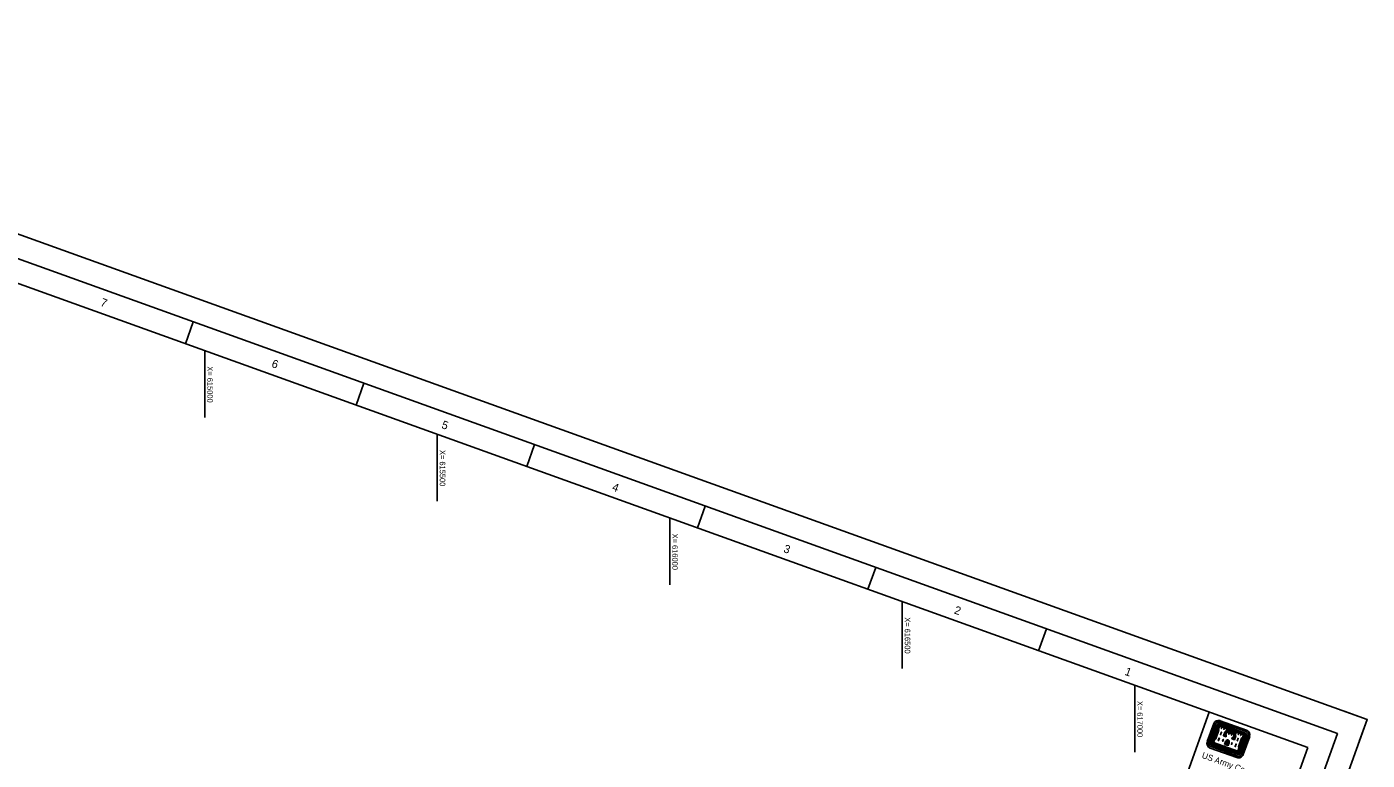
# Model space of a CAD drawing. Extents: x 612209 to 617500, y 780934 to 785622.
# Drawn here: x 614617 to 617500, y 784046 to 785622 of the extents above; entities that cross this region are included whole.
import ezdxf

# ---------------------------------------------------------------- set-up
doc = ezdxf.new("R2010")
doc.units = 0
for name, color, linetype in [('G-ANNO-NPLT', 7, 'Continuous'), ('G-ANNO-TEXT-LOGO', 7, 'Continuous'), ('G-ANNO-TEXT-TTLB', 7, 'Continuous'), ('G-ANNO-TTLB', 7, 'Continuous'), ('V-TOPO-COOR-STAT', 7, 'Continuous')]:
    doc.layers.add(name, color=color, linetype=linetype)

msp = doc.modelspace()

# ---------------------------------------------------------------- linework, layer by layer
at = {"layer": 'G-ANNO-NPLT'}
msp.add_lwpolyline([(613359.5, 785622.2), (617500, 784133.6), (616349.7, 780934.1), (612209.2, 782422.8)], close=True, dxfattribs=at)
msp.add_lwpolyline([(617483.1, 784086.6), (617500, 784133.6), (617453, 784150.5)], dxfattribs=at)
at = {"layer": 'G-ANNO-TEXT-LOGO'}
for p, q in [((617182.5, 784128.1), (617239.7, 784107.6)), ((617240.8, 784110.6), (617183.6, 784131.1)), ((617169.9, 784124.7), (617156, 784086.1)), ((617159.1, 784085), (617172.9, 784123.6)), ((617176.2, 784122.4), (617162.3, 784083.8)), ((617177.1, 784122.1), (617163.2, 784083.5)), ((617177.8, 784121.9), (617163.9, 784083.3)), ((617178.7, 784121.5), (617164.8, 784083)), ((617179.5, 784121.2), (617165.6, 784082.7)), ((617180.4, 784120.9), (617166.6, 784082.6)), ((617181.1, 784120.7), (617167.6, 784083.2)), ((617178.8, 784112.2), (617171.7, 784092.5)), ((617179.4, 784111.1), (617172.9, 784093.1)), ((617237.4, 784101.1), (617180.2, 784121.6)), ((617237.7, 784101.9), (617180.5, 784122.5)), ((617238, 784102.7), (617180.8, 784123.2)), ((617238.3, 784103.5), (617181.1, 784124.1)), ((617238.6, 784104.4), (617181.4, 784124.9)), ((617198, 784108.9), (617215.5, 784102.6)), ((617198.3, 784109.7), (617215.8, 784103.4)), ((617198.6, 784110.5), (617216.1, 784104.2)), ((617198.9, 784111.3), (617216.4, 784105)), ((617199.2, 784112.1), (617216.7, 784105.9)), ((617199.5, 784112.9), (617217, 784106.6)), ((617199.8, 784113.7), (617217.3, 784107.5)), ((617236.1, 784100.9), (617222.6, 784063.5)), ((617236.8, 784100.6), (617223, 784062.3)), ((617237.7, 784100.3), (617223.8, 784061.8)), ((617238.5, 784100), (617224.6, 784061.4)), ((617239.3, 784099.8), (617225.4, 784061.2)), ((617240.1, 784099.5), (617226.2, 784060.9)), ((617241, 784099.2), (617227.1, 784060.6)), ((617244.2, 784098), (617230.3, 784059.4)), ((617162.5, 784072.3), (617219.7, 784051.8)), ((617220.8, 784054.9), (617163.6, 784075.4)), ((617222, 784058.2), (617164.8, 784078.7)), ((617222.2, 784058.9), (617165, 784079.5)), ((617222.5, 784059.8), (617165.3, 784080.3)), ((617222.8, 784060.6), (617165.6, 784081.2)), ((617223.1, 784061.4), (617165.9, 784081.9)), ((617223, 784062.3), (617166.6, 784082.6)), ((617222.6, 784063.5), (617167.6, 784083.2)), ((617193.4, 784080.2), (617195.6, 784086.5)), ((617193.4, 784080.2), (617200.9, 784077.5)), ((617194.1, 784080), (617196.4, 784086.3)), ((617195, 784079.7), (617197.2, 784086)), ((617195.8, 784079.4), (617198.1, 784085.7)), ((617196.6, 784079.1), (617198.8, 784085.4)), ((617197.7, 784078.7), (617199.9, 784085)), ((617198.4, 784078.4), (617200.7, 784084.7)), ((617199.3, 784078.1), (617201.5, 784084.4)), ((617200.1, 784077.8), (617202.4, 784084.1)), ((617200.9, 784077.5), (617203.1, 784083.8)), ((617231.3, 784092.4), (617224.8, 784074.4)), ((617232.4, 784092.9), (617225.4, 784073.3)), ((617233.4, 784058.3), (617247.3, 784096.9))]:
    msp.add_line(p, q, dxfattribs=at)
for points in [[(617181.8, 784120.4), (617179.1, 784113), (617180.1, 784110.8), (617173.7, 784092.8), (617171.4, 784091.7), (617168.5, 784083.5), (617222.1, 784064.3), (617225.1, 784072.4), (617224, 784074.7), (617230.5, 784092.7), (617232.7, 784093.7), (617235.4, 784101.1), (617228.3, 784103.7), (617222.9, 784105.6), (617217.8, 784107.5), (617215.1, 784100), (617216.3, 784097.8), (617214, 784091.2), (617210, 784092.6), (617210.3, 784093.3), (617212.6, 784094.4), (617215.2, 784101.7), (617208.1, 784104.3), (617202.7, 784106.2), (617197.7, 784108), (617195.1, 784100.7), (617196.1, 784098.4), (617195.9, 784097.7), (617192, 784099.1), (617194.3, 784105.7), (617196.6, 784106.7), (617199.3, 784114.1), (617192.2, 784116.7), (617186.8, 784118.6), (617181.8, 784120.4)], [(617182.2, 784119.3), (617180, 784113.1), (617181.1, 784110.8), (617174.4, 784092.2), (617172.1, 784091.1), (617169.6, 784084.1), (617221.7, 784065.4), (617224.2, 784072.3), (617223, 784074.7), (617229.7, 784093.3), (617232.1, 784094.4), (617234.3, 784100.6), (617229.3, 784102.4), (617228.2, 784099.5), (617227.7, 784099.6), (617228.8, 784102.6), (617223.8, 784104.4), (617222.8, 784101.4), (617222.4, 784101.6), (617223.4, 784104.5), (617218.4, 784106.3), (617216.1, 784100.1), (617217.2, 784097.8), (617214.5, 784090.2), (617209, 784092.1), (617209.6, 784093.9), (617211.9, 784095), (617214.2, 784101.2), (617209.1, 784103.1), (617208.1, 784100.1), (617207.7, 784100.3), (617208.7, 784103.2), (617203.6, 784105), (617202.6, 784102.1), (617202.1, 784102.3), (617203.2, 784105.2), (617198.2, 784107), (617196, 784100.8), (617197, 784098.5), (617196.4, 784096.7), (617190.9, 784098.6), (617193.7, 784106.3), (617196, 784107.4), (617198.2, 784113.6), (617193.2, 784115.4), (617192.2, 784112.4), (617191.7, 784112.6), (617192.8, 784115.5), (617187.7, 784117.4), (617186.6, 784114.4), (617186.2, 784114.6), (617187.3, 784117.5), (617182.2, 784119.3)], [(617186.3, 784106.5), (617184.3, 784101), (617184.9, 784100.8), (617186.9, 784106.3), (617186.3, 784106.5)], [(617195.7, 784105.3), (617195, 784105), (617193.1, 784099.7), (617194.9, 784099), (617194.1, 784100.7), (617195.8, 784105.4)], [(617215.1, 784098.4), (617215.4, 784097.7), (617213.4, 784092.4), (617211.7, 784093), (617213.3, 784093.8), (617215, 784098.5)], [(617181.8, 784094), (617179.8, 784088.4), (617180.4, 784088.2), (617182.4, 784093.8), (617181.8, 784094)], [(617190.5, 784090.8), (617189.1, 784087), (617189.6, 784086.8), (617190.9, 784090.7), (617190.5, 784090.8)], [(617209.9, 784083.9), (617208.5, 784080), (617208, 784080.2), (617209.4, 784084), (617209.9, 784083.9)], [(617218.4, 784080.8), (617216.4, 784075.2), (617216, 784075.4), (617217.9, 784081), (617218.4, 784080.8)], [(617222.9, 784093.3), (617221, 784087.9), (617220.5, 784088), (617222.4, 784093.5), (617222.9, 784093.3)]]:
    msp.add_lwpolyline(points, dxfattribs=at)
for centre, major_axis, start_param, end_param in [((617180, 784121.1), (10.1, -3.6), 1.57078, 3.141576), ((617180, 784121.1), (7.05, -2.53), 1.57078, 3.141576), ((617180, 784121.1), (3.78, -1.36), 1.57078, 3.141576), ((617180, 784121.1), (2.96, -1.07), 1.57078, 3.141576), ((617180, 784121.1), (2.15, -0.77), 1.57078, 3.141576), ((617180, 784121.1), (1.33, -0.48), 1.57078, 3.141576), ((617180, 784121.1), (0.513, -0.185), 1.57078, 3.141576), ((617237.1, 784100.5), (0.513, -0.185), 6.283169, 7.853965), ((617237.1, 784100.5), (1.33, -0.48), 6.283169, 7.853965), ((617237.1, 784100.5), (2.15, -0.77), 6.283169, 7.853965), ((617237.1, 784100.5), (2.96, -1.07), 6.283169, 7.853965), ((617237.1, 784100.5), (3.78, -1.36), 6.283169, 7.853965), ((617237.1, 784100.5), (7.05, -2.53), 6.28317, 7.853966), ((617237.1, 784100.5), (10.1, -3.6), 6.283169, 7.853965), ((617166.1, 784082.4), (-10.1, 3.6), 6.28317, 7.853966), ((617166.1, 784082.4), (-7.05, 2.53), 6.28317, 7.853966), ((617166.1, 784082.4), (-3.78, 1.36), 6.28317, 7.853966), ((617166.1, 784082.4), (-2.96, 1.07), 6.28317, 7.853966), ((617166.1, 784082.4), (-2.15, 0.77), 6.28317, 7.853966), ((617166.1, 784082.4), (-1.33, 0.48), 6.28317, 7.853966), ((617166.1, 784082.4), (-0.513, 0.185), 6.28317, 7.853966), ((617200.6, 784084.3), (-5.23, 1.88), 4.985832, 6.214359), ((617200.6, 784084.3), (-4.41, 1.59), 4.947465, 6.21436), ((617200.6, 784084.3), (-3.59, 1.29), 4.947465, 6.21436), ((617200.6, 784084.3), (-2.78, 1), 4.947465, 6.21436), ((617200.6, 784084.3), (-1.96, 0.7), 4.947465, 6.214359), ((617197.8, 784085.3), (1.96, -0.7), 0.068794, 1.335689), ((617197.8, 784085.3), (2.78, -1), 0.068794, 1.335689), ((617197.8, 784085.3), (3.59, -1.29), 0.068795, 1.335689), ((617197.8, 784085.3), (4.41, -1.59), 0.068795, 1.335689), ((617197.8, 784085.3), (5.23, -1.88), 0.068795, 1.29842), ((617223.2, 784061.9), (10.1, -3.6), 4.712373, 6.28317), ((617223.2, 784061.9), (-7.05, 2.53), 1.570781, 3.141577), ((617223.2, 784061.9), (3.78, -1.36), 4.712373, 6.28317), ((617223.2, 784061.9), (2.96, -1.07), 4.712373, 6.28317), ((617223.2, 784061.9), (2.15, -0.77), 4.712373, 6.28317), ((617223.2, 784061.9), (1.33, -0.48), 4.712373, 6.28317), ((617223.2, 784061.9), (0.513, -0.185), 4.712373, 6.28317)]:
    msp.add_ellipse(centre, major_axis=major_axis, ratio=0.99964, start_param=start_param, end_param=end_param, dxfattribs=at)
at = {"layer": 'G-ANNO-TTLB'}
for p, q in [((614975.3, 784988.2), (614958.4, 784941.1)), ((615342.3, 784856.3), (615325.4, 784809.2)), ((615709.3, 784724.3), (615692.4, 784677.3)), ((616076.3, 784592.4), (616059.4, 784545.3)), ((616443.3, 784460.4), (616426.4, 784413.4)), ((616810.3, 784328.5), (616793.4, 784281.4)), ((617160.3, 784149.5), (616077.7, 781138.2))]:
    msp.add_line(p, q, dxfattribs=at)
for points in [[(612273.2, 782452.9), (616319.6, 780998.1), (617436.1, 784103.5), (613389.7, 785558.3)], [(617372.1, 784073.3), (613490.4, 785468.9), (612407.7, 782457.7), (616289.5, 781062.1)]]:
    msp.add_lwpolyline(points, close=True, dxfattribs=at)
at = {"layer": 'V-TOPO-COOR-STAT'}
for p, q in [((615000, 784782.7), (615000, 784926.2)), ((615500, 784603), (615500, 784746.4)), ((616000, 784423.2), (616000, 784566.7)), ((616500, 784243.4), (616500, 784386.9)), ((617000, 784063.7), (617000, 784207.1))]:
    msp.add_line(p, q, dxfattribs=at)

# ---------------------------------------------------------------- texts
at = {"layer": 'G-ANNO-TEXT-TTLB'}
msp.add_text('US Army Corps', height=13.086, rotation=340.2251, dxfattribs=at).set_placement((617143.2, 784051.5))
at = {"layer": 'G-ANNO-TTLB'}
for s, p in [('7', (614774.2, 785023.3)), ('6', (615142.3, 784891.7)), ('5', (615507.8, 784760.3)), ('4', (615874.6, 784626.4)), ('3', (616243.2, 784493.9)), ('2', (616610.3, 784362)), ('1', (616977.2, 784230))]:
    msp.add_text(s, height=17.5, rotation=340.2251, dxfattribs=at).set_placement(p)
at = {"layer": 'V-TOPO-COOR-STAT'}
for s, p in [('X= 615000', (615005.4, 784892.6)), ('X= 615500', (615505.4, 784712.8)), ('X= 616000', (616005.4, 784533.1)), ('X= 616500', (616505.4, 784353.3)), ('X= 617000', (617005.4, 784173.6))]:
    msp.add_text(s, height=12, rotation=270, dxfattribs=at).set_placement(p)

doc.saveas('drawing.dxf')
